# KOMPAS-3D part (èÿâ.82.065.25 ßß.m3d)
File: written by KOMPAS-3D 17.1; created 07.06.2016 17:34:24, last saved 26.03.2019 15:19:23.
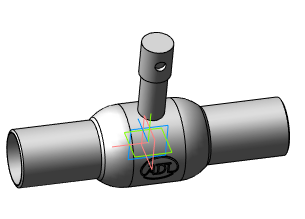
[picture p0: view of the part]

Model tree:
1. Операция без истории:5  (labels: Сталь 20  ГОСТ 1050-88)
